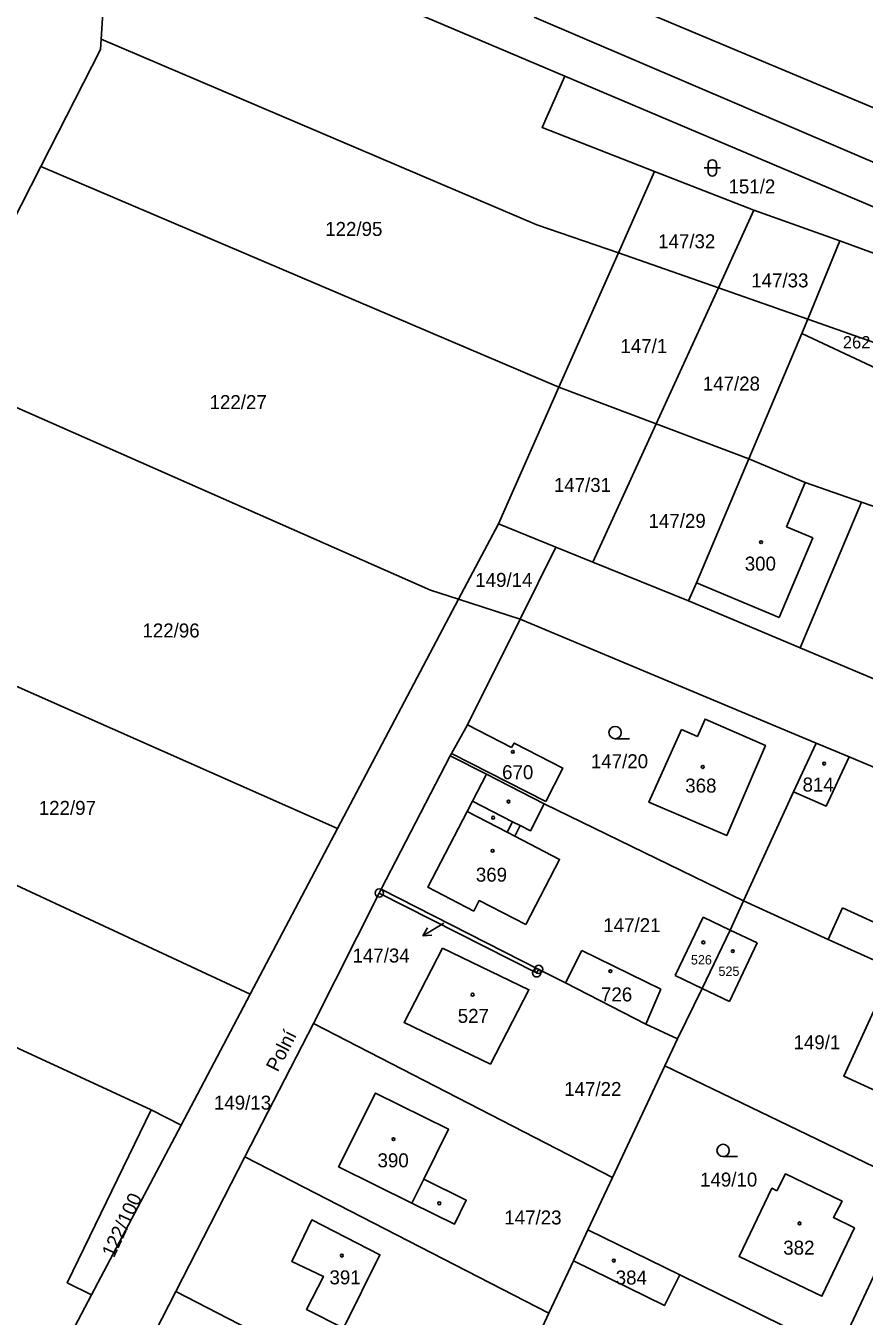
# Model space of a CAD drawing. Extents: x -783948 to -781889, y -1005870 to -1004430.
# Drawn here: x -783122 to -783020.1, y -1005140.8 to -1004983.9 of the extents above; entities that cross this region are included whole.
import ezdxf

# ---------------------------------------------------------------- set-up
doc = ezdxf.new("R2010")
doc.units = 0
for name, color, linetype in [('Vrstva 1', 7, 'Continuous'), ('Vrstva 2', 7, 'Continuous'), ('Vrstva 3', 7, 'Continuous'), ('Vrstva 4', 7, 'Continuous'), ('Vrstva 5', 7, 'Continuous'), ('Vrstva 6', 7, 'Continuous'), ('Vrstva 7', 7, 'Continuous'), ('Vrstva 8', 7, 'Continuous')]:
    doc.layers.add(name, color=color, linetype=linetype)

msp = doc.modelspace()

# ---------------------------------------------------------------- linework, layer by layer
at = {"layer": 'Vrstva 1'}
for p, q in [((-782953.56, -1005021.28), (-783115.01, -1004953.5)), ((-783056.45, -1004989.98), (-783120, -1004963.02)), ((-783112.34, -1004978.43), (-783112.79, -1004985.51)), ((-783120.14, -1005000.99), (-783123.71, -1005007.98)), ((-783057.17, -1005027.81), (-783120.14, -1005000.99)), ((-783049.93, -1005011.47), (-783045.55, -1005001.57)), ((-783045.55, -1005001.57), (-783033.47, -1005006.29)), ((-783033.47, -1005006.29), (-783037.79, -1005015.73)), ((-783033.47, -1005006.29), (-783023.02, -1005010.02)), ((-783026.93, -1005019.54), (-783023.02, -1005010.02)), ((-783023.02, -1005010.02), (-783014.85, -1005013.04)), ((-783049.93, -1005011.47), (-783057.17, -1005027.81)), ((-783037.79, -1005015.73), (-783049.93, -1005011.47)), ((-783045.36, -1005032.26), (-783037.79, -1005015.73)), ((-783026.93, -1005019.54), (-783037.79, -1005015.73)), ((-783027.65, -1005021.28), (-783026.93, -1005019.54)), ((-783034.1, -1005036.5), (-783027.65, -1005021.28)), ((-783064.53, -1005044.43), (-783057.17, -1005027.81)), ((-783057.17, -1005027.81), (-783045.36, -1005032.26)), ((-783053.06, -1005049.08), (-783045.36, -1005032.26)), ((-783045.36, -1005032.26), (-783034.1, -1005036.5)), ((-783027.87, -1005059.51), (-783020.39, -1005041.77)), ((-783006.14, -1005046.74), (-783020.39, -1005041.77)), ((-783069.36, -1005053.58), (-783064.53, -1005044.43)), ((-783064.53, -1005044.43), (-783057.54, -1005047.27)), ((-783057.54, -1005047.27), (-783061.88, -1005056)), ((-783053.06, -1005049.08), (-783057.54, -1005047.27)), ((-783041.43, -1005053.8), (-783053.06, -1005049.08)), ((-783069.36, -1005053.58), (-783084.07, -1005081.46)), ((-783061.88, -1005056), (-783069.36, -1005053.58)), ((-783041.43, -1005053.8), (-783027.87, -1005059.51)), ((-783061.88, -1005056), (-783068.28, -1005068.87)), ((-783025.92, -1005071.09), (-783061.88, -1005056)), ((-783013.98, -1005065.35), (-783027.87, -1005059.51)), ((-783068.28, -1005068.87), (-783070.23, -1005072.36)), ((-783062.92, -1005071.62), (-783068.28, -1005068.87)), ((-783159.66, -1005071.37), (-783094.7, -1005101.6)), ((-783070.23, -1005072.36), (-783070.38, -1005072.63)), ((-783070.23, -1005072.36), (-783058.77, -1005078.19)), ((-783028.65, -1005077.01), (-783025.92, -1005071.09)), ((-783025.92, -1005071.09), (-783021.91, -1005072.77)), ((-783070.38, -1005072.63), (-783078.78, -1005088.86)), ((-783070.38, -1005072.63), (-783065.98, -1005074.86)), ((-782994.76, -1005084.16), (-783021.91, -1005072.77)), ((-783058.95, -1005078.47), (-783065.98, -1005074.86)), ((-783034.76, -1005090.27), (-783028.65, -1005077.01)), ((-783058.95, -1005078.47), (-783034.76, -1005090.27)), ((-783084.07, -1005081.46), (-783094.7, -1005101.6)), ((-783168.85, -1005087.02), (-783106.73, -1005115.68)), ((-783079.01, -1005089.31), (-783086.99, -1005105.19)), ((-783079.01, -1005089.31), (-783078.78, -1005088.86)), ((-783078.78, -1005088.86), (-783059.63, -1005098.59)), ((-783036.38, -1005093.82), (-783034.76, -1005090.27)), ((-783034.76, -1005090.27), (-783024.44, -1005094.96)), ((-783022.7, -1005091.12), (-783024.44, -1005094.96)), ((-783010.64, -1005096.66), (-783022.7, -1005091.12)), ((-783039.66, -1005092.25), (-783043.05, -1005099.34)), ((-783036.38, -1005093.82), (-783039.66, -1005092.25)), ((-783036.38, -1005093.82), (-783039.75, -1005100.91)), ((-783033.09, -1005095.38), (-783036.38, -1005093.82)), ((-783036.46, -1005102.48), (-783033.09, -1005095.38)), ((-783024.44, -1005094.96), (-783012.33, -1005100.45)), ((-783054.37, -1005096.28), (-783056.36, -1005100.25)), ((-783044.8, -1005101), (-783054.37, -1005096.28)), ((-783059.63, -1005098.59), (-783056.36, -1005100.25)), ((-783056.36, -1005100.25), (-783046.6, -1005105.27)), ((-783043.05, -1005099.34), (-783039.75, -1005100.91)), ((-783094.7, -1005101.6), (-783103.1, -1005117.52)), ((-783046.6, -1005105.27), (-783044.8, -1005101)), ((-783042.75, -1005107.03), (-783039.75, -1005100.91)), ((-783039.75, -1005100.91), (-783036.46, -1005102.48)), ((-783086.99, -1005105.19), (-783095.33, -1005121.4)), ((-783086.99, -1005105.19), (-783050.65, -1005123.88)), ((-783046.6, -1005105.27), (-783042.75, -1005107.03)), ((-783044.29, -1005110.32), (-783042.75, -1005107.03)), ((-783050.65, -1005123.88), (-783044.29, -1005110.32)), ((-783044.29, -1005110.32), (-783013.87, -1005125.04)), ((-783106.73, -1005115.68), (-783103.1, -1005117.52)), ((-783103.1, -1005117.52), (-783113.99, -1005138.16)), ((-783095.33, -1005121.4), (-783103.75, -1005137.75)), ((-783095.33, -1005121.4), (-783058.4, -1005140.4)), ((-783053.64, -1005130.25), (-783050.65, -1005123.88)), ((-783013.87, -1005125.04), (-783023.28, -1005145.16)), ((-783053.64, -1005130.25), (-783055.42, -1005134.04)), ((-783042.48, -1005135.73), (-783053.64, -1005130.25)), ((-783058.4, -1005140.4), (-783055.42, -1005134.04)), ((-783042.48, -1005135.73), (-783023.28, -1005145.16)), ((-783113.99, -1005138.16), (-783132.02, -1005172.33)), ((-783103.75, -1005137.75), (-783112.53, -1005154.93)), ((-783103.75, -1005137.75), (-783082.28, -1005148.79)), ((-783063.34, -1005150.93), (-783058.4, -1005140.4))]:
    msp.add_line(p, q, dxfattribs=at)
for points in [[(-783112.79, -1004985.51), (-783112.87, -1004986.76), (-783120.14, -1005000.99)], [(-783112.79, -1004985.51), (-783059.87, -1005008.07), (-783049.93, -1005011.47)], [(-783045.55, -1005001.57), (-783059.22, -1004996.23), (-783056.45, -1004989.98)], [(-783014.85, -1005013.04), (-783012.76, -1005008.51), (-783056.45, -1004989.98)], [(-782998.86, -1005029.87), (-783010.46, -1005025.33), (-783026.93, -1005019.54)], [(-782999.94, -1005032.04), (-783018.56, -1005025.52), (-783027.65, -1005021.28)], [(-783133.13, -1005025.87), (-783072.79, -1005052.47), (-783069.36, -1005053.58)], [(-783034.1, -1005036.5), (-783040.47, -1005051.61), (-783041.43, -1005053.8)], [(-783020.39, -1005041.77), (-783027.24, -1005039.38), (-783034.1, -1005036.5)], [(-783148.87, -1005053.52), (-783126.73, -1005062.56), (-783084.07, -1005081.46)], [(-783042.29, -1005069.44), (-783040.34, -1005070.27), (-783039.41, -1005068.16), (-783032.07, -1005071.36), (-783036.77, -1005082.33), (-783046.24, -1005078.27), (-783042.29, -1005069.44)], [(-783058.77, -1005078.19), (-783056.7, -1005074.11), (-783062.61, -1005071.08), (-783062.92, -1005071.62)], [(-783021.91, -1005072.77), (-783024.7, -1005078.75), (-783028.65, -1005077.01)], [(-783065.98, -1005074.86), (-783067.66, -1005078.14), (-783068.31, -1005079.41), (-783073.09, -1005088.6), (-783067.53, -1005091.5)], [(-783061.21, -1005093.13), (-783057.09, -1005085.22), (-783062.53, -1005082.39), (-783061.88, -1005081.12), (-783060.63, -1005081.76), (-783058.95, -1005078.47)], [(-783059.63, -1005098.59), (-783059.88, -1005099.02), (-783079.01, -1005089.31)], [(-783067.53, -1005091.5), (-783066.87, -1005090.22), (-783061.21, -1005093.13)], [(-783071.31, -1005096.01), (-783075.99, -1005105.04), (-783065.5, -1005110.11), (-783060.82, -1005101.08), (-783071.31, -1005096.01)], [(-783018.2, -1005102.12), (-783010.19, -1005105.74), (-783014.61, -1005115.24), (-783022.55, -1005111.59), (-783018.2, -1005102.12)], [(-783073.59, -1005124.1), (-783068.43, -1005126.67), (-783069.88, -1005129.59), (-783075.04, -1005127.02), (-783083.95, -1005122.59), (-783079.46, -1005113.64), (-783070.58, -1005118.04), (-783073.59, -1005124.1)], [(-783113.99, -1005138.16), (-783116.93, -1005136.69), (-783106.73, -1005115.68)], [(-783030.67, -1005125.51), (-783029.65, -1005123.46), (-783022.75, -1005126.76), (-783023.82, -1005128.76), (-783021.26, -1005130.02), (-783025.21, -1005138.34), (-783035.27, -1005133.49), (-783031.29, -1005125.21), (-783030.67, -1005125.51)], [(-783083.35, -1005142.2), (-783087.83, -1005139.94), (-783085.8, -1005135.93), (-783089.62, -1005134.12), (-783087.21, -1005129.06), (-783078.92, -1005133.29), (-783083.35, -1005142.2)], [(-783055.42, -1005134.04), (-783044.35, -1005139.47), (-783042.48, -1005135.73)]]:
    msp.add_lwpolyline(points, dxfattribs=at)
at = {"layer": 'Vrstva 3'}
for p, q in [((-783039.53, -1005001.15), (-783037.53, -1005001.15)), ((-783039.03, -1005000.65), (-783039.03, -1005001.65)), ((-783038.03, -1005001.65), (-783038.03, -1005000.65)), ((-783050.34, -1005070.56), (-783048.59, -1005070.56)), ((-783037.22, -1005121.36), (-783035.47, -1005121.36))]:
    msp.add_line(p, q, dxfattribs=at)
for centre in [(-783050.34, -1005069.81), (-783037.22, -1005120.61)]:
    msp.add_circle(centre, 0.75, dxfattribs=at)
for centre, start, end in [((-783038.53, -1005000.65), 0, 180), ((-783038.53, -1005001.65), 180, 359.9879)]:
    msp.add_arc(centre, 0.5, start, end, dxfattribs=at)
at = {"layer": 'Vrstva 4'}
for p, q in [((-783027.24, -1005039.38), (-783029.51, -1005044.77)), ((-783029.51, -1005044.77), (-783026.33, -1005046.11)), ((-783026.33, -1005046.11), (-783030.42, -1005055.83)), ((-783040.47, -1005051.61), (-783030.42, -1005055.83)), ((-783067.66, -1005078.14), (-783062.81, -1005080.64)), ((-783068.31, -1005079.41), (-783063.46, -1005081.91)), ((-783063.46, -1005081.91), (-783062.81, -1005080.64)), ((-783063.46, -1005081.91), (-783062.53, -1005082.39)), ((-783062.81, -1005080.64), (-783061.88, -1005081.12)), ((-783073.59, -1005124.1), (-783075.04, -1005127.02))]:
    msp.add_line(p, q, dxfattribs=at)
at = {"layer": 'Vrstva 5'}
for centre in [(-783032.61, -1005046.65), (-783062.77, -1005072.15), (-783039.7, -1005073.98), (-783024.94, -1005073.58), (-783063.3, -1005078.2), (-783065.17, -1005080.15), (-783065.23, -1005084.18), (-783039.62, -1005095.31), (-783036.04, -1005096.38), (-783050.92, -1005098.81), (-783067.66, -1005101.67), (-783077.28, -1005119.24), (-783071.71, -1005127.04), (-783027.93, -1005129.48), (-783083.55, -1005133.4), (-783050.5, -1005134)]:
    msp.add_circle(centre, 0.175, dxfattribs=at)
at = {"layer": 'Vrstva 6'}
msp.add_line((-783060.19, -1004982.81), (-782841.72, -1005076.44), dxfattribs=at)
at = {"layer": 'Vrstva 7'}
for p, q in [((-783071.16, -1005092.96), (-783073.73, -1005094.51)), ((-783073.73, -1005094.51), (-783073.13, -1005093.56)), ((-783073.73, -1005094.51), (-783072.62, -1005094.42))]:
    msp.add_line(p, q, dxfattribs=at)
at = {"layer": 'Vrstva 8'}
for centre, radius in [((-783079.01, -1005089.31), 0.5), ((-783079.01, -1005089.31), 0.0303), ((-783059.88, -1005099.02), 0.5), ((-783059.63, -1005098.59), 0.5), ((-783059.88, -1005099.02), 0.0303), ((-783059.63, -1005098.59), 0.0303)]:
    msp.add_circle(centre, radius, dxfattribs=at)

# ---------------------------------------------------------------- texts
at = {"layer": 'Vrstva 2'}
for s, height, p in [('151/2', 1.7, (-783036.56, -1005004.25)), ('122/95', 1.7, (-783085.58, -1005009.42)), ('147/32', 1.7, (-783045.12, -1005010.92)), ('147/33', 1.7, (-783033.8, -1005015.67)), ('147/1', 1.7, (-783049.7, -1005023.66)), ('147/28', 1.7, (-783039.69, -1005028.22)), ('122/27', 1.7, (-783099.63, -1005030.47)), ('147/31', 1.7, (-783057.79, -1005040.55)), ('147/29', 1.7, (-783046.28, -1005044.91)), ('300', 1.7, (-783034.59, -1005050.11)), ('149/14', 1.7, (-783067.34, -1005052.09)), ('122/96', 1.7, (-783107.79, -1005058.24)), ('147/20', 1.7, (-783053.29, -1005074.14)), ('670', 1.7, (-783064.08, -1005075.47)), ('368', 1.7, (-783041.82, -1005077.1)), ('814', 1.7, (-783027.56, -1005076.97)), ('122/97', 1.7, (-783120.39, -1005079.81)), ('369', 1.7, (-783067.27, -1005087.93)), ('147/21', 1.7, (-783051.78, -1005094.07)), ('147/34', 1.7, (-783082.26, -1005097.76)), ('526', 1.14, (-783041.13, -1005098)), ('525', 1.14, (-783037.78, -1005099.39)), ('726', 1.7, (-783052.06, -1005102.49)), ('527', 1.7, (-783069.47, -1005105.1)), ('149/1', 1.7, (-783028.66, -1005108.31)), ('147/22', 1.7, (-783056.53, -1005113.99)), ('149/13', 1.7, (-783099.1, -1005115.65)), ('390', 1.7, (-783079.22, -1005122.66)), ('149/10', 1.7, (-783040.02, -1005125)), ('147/23', 1.7, (-783063.81, -1005129.61)), ('382', 1.7, (-783029.91, -1005133.28)), ('391', 1.7, (-783085.06, -1005136.89)), ('384', 1.7, (-783050.27, -1005136.91))]:
    msp.add_text(s, height=height, dxfattribs=at).set_placement(p)
msp.add_text('122/100', height=1.7, rotation=65, dxfattribs=at).set_placement((-783111.26, -1005133.76))
at = {"layer": 'Vrstva 7'}
msp.add_text('Polní', height=1.7, rotation=63, dxfattribs=at).set_placement((-783091.34, -1005111.17))
at = {"layer": 'Vrstva 8'}
msp.add_text('262', height=1.5, dxfattribs=at).set_placement((-783022.67, -1005023.1))

doc.saveas('drawing.dxf')
